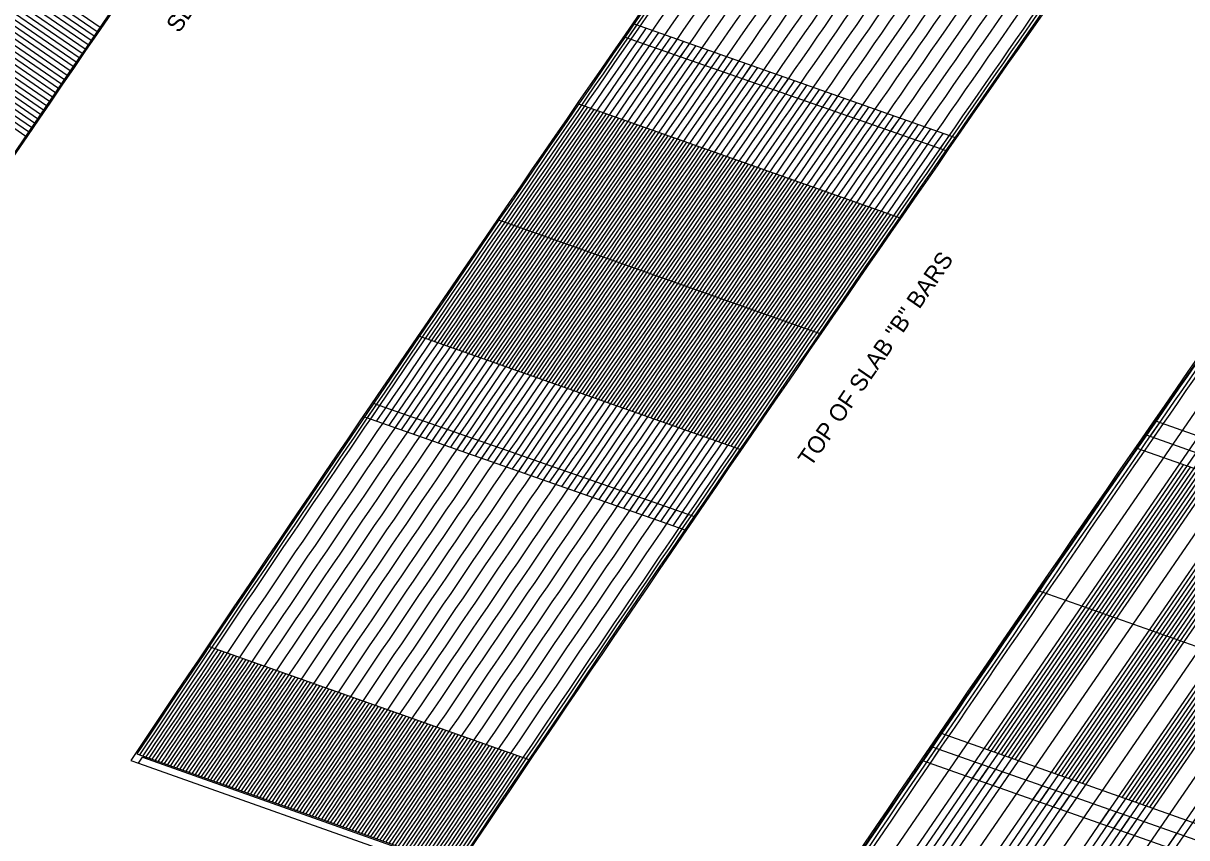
# Model space of a CAD drawing. Extents: x 2378999 to 2381348, y 331302 to 333122.
# Drawn here: x 2379768 to 2379905.9, y 332266.3 to 332362.9 of the extents above; entities that cross this region are included whole.
import ezdxf

# ---------------------------------------------------------------- set-up
doc = ezdxf.new("R2010")
doc.units = 0
for name, color, linetype in [('Arrowhead Terminators', 7, 'Continuous'), ('Mis Work Point CELL', 7, 'Continuous'), ('Old_Level_8', 7, 'Continuous'), ('P_SMU_Concrete_Barrier_Rail', 7, 'Continuous'), ('P_SMU_Mis_L_Lines', 7, 'Continuous'), ('P_SMU_Mis_Long_Chord', 7, 'Continuous'), ('P_SMU_Rebar_B_Bar', 7, 'Continuous'), ('Scratch_Level_0', 7, 'Continuous'), ('Sup Concrete Slab Lines', 7, 'Continuous')]:
    doc.layers.add(name, color=color, linetype=linetype)

msp = doc.modelspace()

# ---------------------------------------------------------------- linework, layer by layer
at = {"layer": 'Arrowhead Terminators'}
for p, q in [((2379879.71, 332273.67), (2379907.36, 332313.92)), ((2379880.53, 332273.39), (2379908.18, 332313.63)), ((2379881.34, 332273.1), (2379908.99, 332313.35)), ((2379882.15, 332272.81), (2379909.8, 332313.06)), ((2379882.97, 332272.52), (2379910.62, 332312.77)), ((2379883.78, 332272.23), (2379911.43, 332312.48)), ((2379887.68, 332270.85), (2379915.34, 332311.1)), ((2379882.34, 332276.76), (2379905.55, 332310.55)), ((2379883.15, 332276.47), (2379906.37, 332310.26)), ((2379883.96, 332276.18), (2379907.18, 332309.97)), ((2379884.78, 332275.89), (2379907.99, 332309.69)), ((2379888.5, 332270.56), (2379916.15, 332310.81)), ((2379889.31, 332270.28), (2379916.96, 332310.53)), ((2379890.12, 332269.99), (2379917.78, 332310.24)), ((2379890.94, 332269.7), (2379918.59, 332309.95)), ((2379885.59, 332275.61), (2379908.81, 332309.4)), ((2379891.75, 332269.41), (2379919.4, 332309.66)), ((2379890.31, 332273.94), (2379913.52, 332307.73)), ((2379891.12, 332273.65), (2379914.34, 332307.44)), ((2379891.93, 332273.36), (2379915.15, 332307.15)), ((2379895.65, 332268.03), (2379923.31, 332308.28)), ((2379896.47, 332267.74), (2379924.12, 332307.99)), ((2379897.28, 332267.46), (2379924.93, 332307.7)), ((2379898.09, 332267.17), (2379925.75, 332307.42)), ((2379898.91, 332266.88), (2379926.56, 332307.13)), ((2379892.75, 332273.07), (2379915.96, 332306.87)), ((2379893.56, 332272.78), (2379916.78, 332306.58)), ((2379899.72, 332266.59), (2379927.37, 332306.84)), ((2379898.28, 332271.12), (2379921.49, 332304.91)), ((2379899.09, 332270.83), (2379922.31, 332304.62)), ((2379899.9, 332270.54), (2379923.12, 332304.33)), ((2379903.62, 332265.21), (2379931.28, 332305.46)), ((2379904.44, 332264.92), (2379932.09, 332305.17)), ((2379900.72, 332270.25), (2379923.93, 332304.04)), ((2379901.53, 332269.96), (2379924.75, 332303.76)), ((2379850.18, 332230.68), (2379880.84, 332275.32)), ((2379850.99, 332230.39), (2379881.66, 332275.03)), ((2379851.8, 332230.11), (2379882.47, 332274.75)), ((2379852.61, 332229.82), (2379883.28, 332274.46)), ((2379853.43, 332229.53), (2379884.1, 332274.17)), ((2379854.24, 332229.24), (2379884.91, 332273.88)), ((2379858.15, 332227.86), (2379888.81, 332272.5)), ((2379858.96, 332227.57), (2379889.63, 332272.21)), ((2379859.77, 332227.29), (2379890.44, 332271.92)), ((2379860.59, 332227), (2379891.25, 332271.64)), ((2379861.4, 332226.71), (2379892.07, 332271.35)), ((2379862.21, 332226.42), (2379892.88, 332271.06)), ((2379866.12, 332225.04), (2379896.78, 332269.68)), ((2379866.93, 332224.75), (2379897.6, 332269.39)), ((2379867.74, 332224.46), (2379898.41, 332269.1)), ((2379868.56, 332224.18), (2379899.22, 332268.82)), ((2379869.37, 332223.89), (2379900.04, 332268.53)), ((2379870.18, 332223.6), (2379900.85, 332268.24)), ((2379874.09, 332222.22), (2379904.76, 332266.86)), ((2379874.9, 332221.93), (2379905.57, 332266.57))]:
    msp.add_line(p, q, dxfattribs=at)
for centre, radius, start, end in [((2385678.87, 328323.64), 7099.13, 144.933691, 145.338143), ((2385678.87, 328323.64), 7098.75, 144.932847, 145.337324), ((2385678.87, 328323.64), 7097.25, 144.929472, 145.334043), ((2385678.87, 328323.64), 7095.75, 144.926095, 145.330761), ((2385678.87, 328323.64), 7094.25, 144.922716, 145.327478), ((2385678.87, 328323.64), 7092.75, 144.919336, 145.324193), ((2385678.87, 328323.64), 7091.25, 144.915954, 145.320907), ((2385678.87, 328323.64), 7089.75, 144.912571, 145.317619), ((2385678.87, 328323.64), 7088.25, 144.909187, 145.31433), ((2385678.87, 328323.64), 7086.75, 144.9058, 145.31104), ((2385678.87, 328323.64), 7085.25, 144.902413, 145.307748), ((2385678.87, 328323.64), 7083.75, 144.899024, 145.304454), ((2385678.87, 328323.64), 7082.25, 144.895633, 145.301159), ((2385678.87, 328323.64), 7080.75, 144.892241, 145.297863), ((2385678.87, 328323.64), 7079.25, 144.888848, 145.294565), ((2385678.87, 328323.64), 7077.75, 144.885453, 145.291266), ((2385678.87, 328323.64), 7076.25, 144.882056, 145.287965), ((2385678.87, 328323.64), 7074.75, 144.878658, 145.284663), ((2385678.87, 328323.64), 7073.25, 144.875259, 145.28136), ((2385678.87, 328323.64), 7071.75, 144.871858, 145.278055), ((2385678.87, 328323.64), 7070.25, 144.868455, 145.274748), ((2385678.87, 328323.64), 7068.75, 144.865051, 145.27144), ((2385678.87, 328323.64), 7067.25, 144.861645, 145.268131), ((2385678.87, 328323.64), 7065.75, 144.858238, 145.26482), ((2385678.87, 328323.64), 7064.25, 144.85483, 145.261508), ((2385678.87, 328323.64), 7062.75, 144.85142, 145.258194), ((2385678.87, 328323.64), 7061.25, 144.848008, 145.254879), ((2385678.87, 328323.64), 7060.88, 144.847155, 145.25405), ((2385678.87, 328323.64), 7099.13, 145.322674, 145.778676), ((2385678.87, 328323.64), 7098.75, 145.321854, 145.777879), ((2385678.87, 328323.64), 7098, 145.320212, 145.776286), ((2385678.87, 328323.64), 7097.25, 145.31857, 145.774692), ((2385678.87, 328323.64), 7096.5, 145.316927, 145.773098), ((2385678.87, 328323.64), 7095.75, 145.315285, 145.771503), ((2385678.87, 328323.64), 7095, 145.313642, 145.769908), ((2385678.87, 328323.64), 7094.25, 145.311998, 145.768313), ((2385678.87, 328323.64), 7093.5, 145.310354, 145.766717), ((2385678.87, 328323.64), 7092.75, 145.30871, 145.765121), ((2385678.87, 328323.64), 7092, 145.307066, 145.763525), ((2385678.87, 328323.64), 7091.25, 145.305421, 145.761928), ((2385678.87, 328323.64), 7090.5, 145.303775, 145.760331), ((2385678.87, 328323.64), 7089.75, 145.30213, 145.758734), ((2385678.87, 328323.64), 7089, 145.300484, 145.757136), ((2385678.87, 328323.64), 7088.25, 145.298837, 145.755538), ((2385678.87, 328323.64), 7087.5, 145.297191, 145.75394), ((2385678.87, 328323.64), 7086.75, 145.295544, 145.752341), ((2385678.87, 328323.64), 7086, 145.293896, 145.750742), ((2385742.82, 328279.7), 7099.38, 144.934254, 145.370258), ((2385742.82, 328279.7), 7098.96, 144.933316, 145.369348), ((2385742.82, 328279.7), 7098.54, 144.932379, 145.368438), ((2385678.87, 328323.64), 7085.25, 145.292248, 145.749142), ((2385678.87, 328323.64), 7084.5, 145.2906, 145.747543), ((2385678.87, 328323.64), 7083.75, 145.288952, 145.745942), ((2385678.87, 328323.64), 7083, 145.287303, 145.744342), ((2385678.87, 328323.64), 7082.25, 145.285653, 145.742741), ((2385678.87, 328323.64), 7081.5, 145.284004, 145.74114), ((2385678.87, 328323.64), 7080.75, 145.282354, 145.739538), ((2385678.87, 328323.64), 7080, 145.280703, 145.737936), ((2385678.87, 328323.64), 7079.25, 145.279053, 145.736334), ((2385678.87, 328323.64), 7078.5, 145.277402, 145.734731), ((2385678.87, 328323.64), 7077.75, 145.27575, 145.733129), ((2385678.87, 328323.64), 7077, 145.274098, 145.731525), ((2385678.87, 328323.64), 7076.25, 145.272446, 145.729922), ((2385678.87, 328323.64), 7075.5, 145.270794, 145.728317), ((2385678.87, 328323.64), 7074.75, 145.269141, 145.726713), ((2385678.87, 328323.64), 7074, 145.267488, 145.725108), ((2385678.87, 328323.64), 7098.38, 145.41453, 145.683586), ((2385678.87, 328323.64), 7097.63, 145.412898, 145.681982), ((2385678.87, 328323.64), 7073.25, 145.265834, 145.723503), ((2385678.87, 328323.64), 7072.5, 145.26418, 145.721898), ((2385678.87, 328323.64), 7071.75, 145.262526, 145.720292), ((2385678.87, 328323.64), 7071, 145.260871, 145.718686), ((2385678.87, 328323.64), 7070.25, 145.259216, 145.717079), ((2385678.87, 328323.64), 7069.5, 145.25756, 145.715473), ((2385678.87, 328323.64), 7096.88, 145.411265, 145.680378), ((2385678.87, 328323.64), 7096.13, 145.409633, 145.678774), ((2385678.87, 328323.64), 7095.38, 145.408, 145.677169), ((2385678.87, 328323.64), 7094.63, 145.406366, 145.675564), ((2385678.87, 328323.64), 7093.88, 145.404732, 145.673959), ((2385678.87, 328323.64), 7093.13, 145.403098, 145.672353), ((2385678.87, 328323.64), 7068.75, 145.255905, 145.713865), ((2385678.87, 328323.64), 7068, 145.254249, 145.712258), ((2385678.87, 328323.64), 7067.25, 145.252592, 145.71065), ((2385678.87, 328323.64), 7066.5, 145.250935, 145.709042), ((2385678.87, 328323.64), 7065.75, 145.249278, 145.707433), ((2385678.87, 328323.64), 7092.38, 145.401464, 145.670747), ((2385678.87, 328323.64), 7091.63, 145.399829, 145.669141), ((2385678.87, 328323.64), 7090.88, 145.398194, 145.667534), ((2385678.87, 328323.64), 7090.13, 145.396558, 145.665927), ((2385678.87, 328323.64), 7089.38, 145.394922, 145.66432), ((2385678.87, 328323.64), 7065, 145.24762, 145.705824), ((2385678.87, 328323.64), 7064.25, 145.245962, 145.704215), ((2385678.87, 328323.64), 7063.5, 145.244304, 145.702605), ((2385678.87, 328323.64), 7062.75, 145.242645, 145.700995), ((2385678.87, 328323.64), 7062, 145.240986, 145.699385), ((2385678.87, 328323.64), 7088.63, 145.393286, 145.662712), ((2385678.87, 328323.64), 7087.88, 145.391649, 145.661104), ((2385678.87, 328323.64), 7087.13, 145.390012, 145.659495), ((2385678.87, 328323.64), 7086.38, 145.388375, 145.657886), ((2385678.87, 328323.64), 7085.63, 145.386737, 145.656277), ((2385678.87, 328323.64), 7061.25, 145.239327, 145.697774), ((2385678.87, 328323.64), 7060.88, 145.238497, 145.696969), ((2385678.87, 328323.64), 7084.88, 145.385099, 145.654668), ((2385678.87, 328323.64), 7084.13, 145.383461, 145.653058), ((2385678.87, 328323.64), 7083.38, 145.381822, 145.651447), ((2385678.87, 328323.64), 7082.63, 145.380183, 145.649837), ((2385678.87, 328323.64), 7081.88, 145.378543, 145.648226), ((2385678.87, 328323.64), 7081.13, 145.376903, 145.646615), ((2385678.87, 328323.64), 7080.38, 145.375263, 145.645003), ((2385678.87, 328323.64), 7079.63, 145.373623, 145.643391), ((2385678.87, 328323.64), 7078.88, 145.371982, 145.641778), ((2385678.87, 328323.64), 7078.13, 145.37034, 145.640166), ((2385678.87, 328323.64), 7077.38, 145.368699, 145.638553), ((2385678.87, 328323.64), 7076.63, 145.367057, 145.636939), ((2385678.87, 328323.64), 7075.88, 145.365414, 145.635325), ((2385678.87, 328323.64), 7075.13, 145.363771, 145.633711), ((2385678.87, 328323.64), 7074.38, 145.362128, 145.632097), ((2385678.87, 328323.64), 7073.63, 145.360485, 145.630482), ((2385678.87, 328323.64), 7072.88, 145.358841, 145.628867), ((2385678.87, 328323.64), 7072.13, 145.357197, 145.627251), ((2385678.87, 328323.64), 7071.38, 145.355552, 145.625635), ((2385678.87, 328323.64), 7070.63, 145.353907, 145.624019), ((2385678.87, 328323.64), 7069.88, 145.352262, 145.622402), ((2385678.87, 328323.64), 7069.13, 145.350616, 145.620785), ((2385678.87, 328323.64), 7068.38, 145.34897, 145.619168), ((2385678.87, 328323.64), 7067.63, 145.347324, 145.61755), ((2385678.87, 328323.64), 7066.88, 145.345677, 145.615932), ((2385678.87, 328323.64), 7066.13, 145.34403, 145.614314), ((2385678.87, 328323.64), 7065.38, 145.342383, 145.612695), ((2385678.87, 328323.64), 7064.63, 145.340735, 145.611076), ((2385678.87, 328323.64), 7063.88, 145.339087, 145.609456), ((2385678.87, 328323.64), 7063.13, 145.337438, 145.607837), ((2385678.87, 328323.64), 7062.38, 145.335789, 145.606216), ((2385678.87, 328323.64), 7061.63, 145.33414, 145.604596), ((2385678.87, 328323.64), 7099.13, 145.763207, 146.167718), ((2385678.87, 328323.64), 7098.75, 145.762409, 146.166944), ((2385678.87, 328323.64), 7097.25, 145.759219, 146.163848), ((2385678.87, 328323.64), 7095.75, 145.756027, 146.16075), ((2385678.87, 328323.64), 7094.25, 145.752833, 146.157651), ((2385678.87, 328323.64), 7092.75, 145.749638, 146.154551), ((2385742.82, 328279.7), 7099.38, 145.354106, 145.748141), ((2385742.82, 328279.7), 7098.96, 145.353195, 145.747255), ((2385742.82, 328279.7), 7098.54, 145.352284, 145.746369), ((2385678.87, 328323.64), 7091.25, 145.746442, 146.15145), ((2385678.87, 328323.64), 7089.75, 145.743244, 146.148347), ((2385678.87, 328323.64), 7088.25, 145.740045, 146.145242), ((2385678.87, 328323.64), 7086.75, 145.736845, 146.142136), ((2385678.87, 328323.64), 7085.25, 145.733643, 146.139029), ((2385678.87, 328323.64), 7083.75, 145.73044, 146.135921), ((2385678.87, 328323.64), 7082.25, 145.727235, 146.132811), ((2385678.87, 328323.64), 7080.75, 145.724029, 146.1297), ((2385678.87, 328323.64), 7079.25, 145.720822, 146.126588), ((2385678.87, 328323.64), 7077.75, 145.717613, 146.123474), ((2385678.87, 328323.64), 7076.25, 145.714402, 146.120359), ((2385678.87, 328323.64), 7074.75, 145.711191, 146.117242), ((2385678.87, 328323.64), 7073.25, 145.707978, 146.114124), ((2385678.87, 328323.64), 7071.75, 145.704763, 146.111005), ((2385678.87, 328323.64), 7070.25, 145.701547, 146.107884), ((2385678.87, 328323.64), 7068.75, 145.69833, 146.104762), ((2385678.87, 328323.64), 7067.25, 145.695111, 146.101638), ((2385678.87, 328323.64), 7065.75, 145.691891, 146.098514), ((2385678.87, 328323.64), 7064.25, 145.688669, 146.095388), ((2385678.87, 328323.64), 7062.75, 145.685446, 146.09226), ((2385678.87, 328323.64), 7061.25, 145.682222, 146.089131), ((2385678.87, 328323.64), 7060.88, 145.681416, 146.088349), ((2385643.84, 328336.04), 7062.38, 145.967039, 146.091478), ((2385643.84, 328336.04), 7062, 145.966251, 146.090696), ((2385643.84, 328336.04), 7061.63, 145.965462, 146.089913), ((2385645.3, 328335.52), 7062.38, 145.967041, 146.091478), ((2385645.3, 328335.52), 7062, 145.966252, 146.090696), ((2385645.3, 328335.52), 7061.63, 145.965463, 146.089913), ((2385646.76, 328335), 7062.38, 145.967043, 146.091478), ((2385646.76, 328335), 7062, 145.966254, 146.090696), ((2385646.76, 328335), 7061.63, 145.965465, 146.089913), ((2385648.21, 328334.49), 7062.38, 145.967045, 146.091478), ((2385648.21, 328334.49), 7062, 145.966256, 146.090696), ((2385648.21, 328334.49), 7061.63, 145.965467, 146.089913), ((2385649.67, 328333.97), 7062.38, 145.967046, 146.091478), ((2385649.67, 328333.97), 7062, 145.966258, 146.090696), ((2385649.67, 328333.97), 7061.63, 145.965469, 146.089913), ((2385651.13, 328333.45), 7062.38, 145.967048, 146.091478), ((2385651.13, 328333.45), 7062, 145.966259, 146.090696), ((2385651.13, 328333.45), 7061.63, 145.96547, 146.089913), ((2385652.59, 328332.94), 7062.38, 145.96705, 146.091478), ((2385652.59, 328332.94), 7062, 145.966261, 146.090696), ((2385652.59, 328332.94), 7061.63, 145.965472, 146.089913), ((2385654.05, 328332.42), 7062.38, 145.967052, 146.091478), ((2385654.05, 328332.42), 7062, 145.966263, 146.090696), ((2385654.05, 328332.42), 7061.63, 145.965474, 146.089913), ((2385655.51, 328331.9), 7062.38, 145.967053, 146.091478), ((2385655.51, 328331.9), 7062, 145.966265, 146.090696), ((2385655.51, 328331.9), 7061.63, 145.965476, 146.089913), ((2385656.97, 328331.39), 7062.38, 145.967055, 146.091478), ((2385656.97, 328331.39), 7062, 145.966266, 146.090696), ((2385656.97, 328331.39), 7061.63, 145.965477, 146.089913), ((2385658.43, 328330.87), 7062.38, 145.967057, 146.091478), ((2385658.43, 328330.87), 7062, 145.966268, 146.090696), ((2385658.43, 328330.87), 7061.63, 145.965479, 146.089913), ((2385659.89, 328330.35), 7062.38, 145.967059, 146.091478), ((2385659.89, 328330.35), 7062, 145.96627, 146.090696), ((2385659.89, 328330.35), 7061.63, 145.965481, 146.089913), ((2385661.35, 328329.84), 7062.38, 145.96706, 146.091478), ((2385661.35, 328329.84), 7062, 145.966272, 146.090696), ((2385661.35, 328329.84), 7061.63, 145.965483, 146.089913), ((2385662.81, 328329.32), 7062.38, 145.967062, 146.091478), ((2385662.81, 328329.32), 7062, 145.966273, 146.090696), ((2385662.81, 328329.32), 7061.63, 145.965484, 146.089913), ((2385664.27, 328328.8), 7062.38, 145.967064, 146.091478), ((2385664.27, 328328.8), 7062, 145.966275, 146.090696), ((2385664.27, 328328.8), 7061.63, 145.965486, 146.089913), ((2385665.73, 328328.29), 7062.38, 145.967066, 146.091478), ((2385665.73, 328328.29), 7062, 145.966277, 146.090696), ((2385665.73, 328328.29), 7061.63, 145.965488, 146.089913), ((2385667.19, 328327.77), 7062.38, 145.967067, 146.091478), ((2385667.19, 328327.77), 7062, 145.966279, 146.090696), ((2385667.19, 328327.77), 7061.63, 145.96549, 146.089913), ((2385668.65, 328327.25), 7062.38, 145.967069, 146.091478), ((2385668.65, 328327.25), 7062, 145.96628, 146.090696), ((2385668.65, 328327.25), 7061.63, 145.965491, 146.089913), ((2385670.11, 328326.74), 7062.38, 145.967071, 146.091478), ((2385670.11, 328326.74), 7062, 145.966282, 146.090696), ((2385670.11, 328326.74), 7061.63, 145.965493, 146.089913), ((2385671.57, 328326.22), 7062.38, 145.967073, 146.091478), ((2385671.57, 328326.22), 7062, 145.966284, 146.090696), ((2385671.57, 328326.22), 7061.63, 145.965495, 146.089913), ((2385673.03, 328325.7), 7062.38, 145.967074, 146.091478), ((2385673.03, 328325.7), 7062, 145.966286, 146.090696), ((2385673.03, 328325.7), 7061.63, 145.965497, 146.089913), ((2385674.49, 328325.19), 7062.38, 145.967076, 146.091478), ((2385674.49, 328325.19), 7062, 145.966287, 146.090696), ((2385674.49, 328325.19), 7061.63, 145.965498, 146.089913), ((2385675.95, 328324.67), 7062.38, 145.967078, 146.091478), ((2385675.95, 328324.67), 7062, 145.966289, 146.090696), ((2385675.95, 328324.67), 7061.63, 145.9655, 146.089913), ((2385677.41, 328324.15), 7062.38, 145.96708, 146.091478), ((2385677.41, 328324.15), 7062, 145.966291, 146.090696), ((2385742.82, 328279.7), 7099.38, 145.732017, 146.168234), ((2385742.82, 328279.7), 7098.96, 145.73113, 146.167374), ((2385742.82, 328279.7), 7098.54, 145.730243, 146.166514), ((2385677.41, 328324.15), 7061.63, 145.965502, 146.089913), ((2385678.87, 328323.64), 7062.38, 145.967081, 146.091478), ((2385678.87, 328323.64), 7062, 145.966293, 146.090696), ((2385678.87, 328323.64), 7061.63, 145.965504, 146.089913)]:
    msp.add_arc(centre, radius, start, end, dxfattribs=at)
at = {"layer": 'Mis Work Point CELL'}
for p, q in [((2379824.25, 332339.62), (2379862.56, 332326.06)), ((2379888.21, 332295.69), (2379926.51, 332282.13))]:
    msp.add_line(p, q, dxfattribs=at)
at = {"layer": 'Old_Level_8'}
for p, q in [((2379745.06, 332384.46), (2379777.14, 332362.43)), ((2379744.01, 332382.92), (2379776.08, 332360.88)), ((2379744.36, 332383.43), (2379776.43, 332361.39)), ((2379744.71, 332383.95), (2379776.79, 332361.91)), ((2379743.3, 332381.88), (2379775.38, 332359.85)), ((2379743.65, 332382.4), (2379775.73, 332360.36)), ((2379742.24, 332380.34), (2379774.32, 332358.3)), ((2379742.59, 332380.85), (2379774.67, 332358.81)), ((2379742.95, 332381.37), (2379775.02, 332359.33)), ((2379741.18, 332378.79), (2379773.26, 332356.75)), ((2379741.54, 332379.3), (2379773.61, 332357.27)), ((2379741.89, 332379.82), (2379773.97, 332357.78)), ((2379740.48, 332377.76), (2379772.56, 332355.72)), ((2379740.83, 332378.27), (2379772.91, 332356.23)), ((2379739.42, 332376.21), (2379771.5, 332354.17)), ((2379739.78, 332376.72), (2379771.85, 332354.69)), ((2379740.13, 332377.24), (2379772.2, 332355.2)), ((2379738.37, 332374.66), (2379770.44, 332352.62)), ((2379738.72, 332375.17), (2379770.79, 332353.14)), ((2379739.07, 332375.69), (2379771.15, 332353.65)), ((2379737.31, 332373.11), (2379769.39, 332351.07)), ((2379737.66, 332373.62), (2379769.74, 332351.59)), ((2379738.01, 332374.14), (2379770.09, 332352.1)), ((2379736.61, 332372.07), (2379768.68, 332350.04)), ((2379736.96, 332372.59), (2379769.03, 332350.55)), ((2379736.25, 332371.56), (2379768.33, 332349.52))]:
    msp.add_line(p, q, dxfattribs=at)
at = {"layer": 'P_SMU_Concrete_Barrier_Rail'}
for p, q in [((2379780.77, 332275.49), (2379781.71, 332275.16)), ((2379781.71, 332275.16), (2379782.18, 332275.87)), ((2379782.18, 332275.87), (2379818.52, 332263.01)), ((2379782.83, 332275.64), (2379782.18, 332275.87))]:
    msp.add_line(p, q, dxfattribs=at)
for centre, radius, start, end in [((2385604, 328375.08), 7099.63, 144.926438, 146.177079), ((2385604, 328375.08), 7060.38, 144.837589, 146.095684), ((2385678.87, 328323.64), 7099.63, 144.926438, 146.177079), ((2385678.87, 328323.64), 7060.38, 144.837589, 146.095684), ((2385742.82, 328279.7), 7099.63, 144.926438, 146.177079), ((2385742.82, 328279.7), 7060.38, 144.837589, 146.095684)]:
    msp.add_arc(centre, radius, start, end, dxfattribs=at)
at = {"layer": 'P_SMU_Mis_L_Lines'}
for p, q in [((2379891.59, 332294.49), (2379935.41, 332358.27)), ((2379899.56, 332291.67), (2379943.38, 332355.45)), ((2379847.64, 332230.52), (2379891.59, 332294.49)), ((2379855.61, 332227.7), (2379899.56, 332291.67)), ((2379863.58, 332224.88), (2379907.53, 332288.85)), ((2379871.55, 332222.06), (2379915.5, 332286.03))]:
    msp.add_line(p, q, dxfattribs=at)
at = {"layer": 'P_SMU_Mis_Long_Chord'}
msp.add_arc((2385604, 328375.08), 7080, 144.882142, 146.136498, dxfattribs=at)
at = {"layer": 'P_SMU_Rebar_B_Bar'}
msp.add_line((2379781.71, 332275.16), (2379818.04, 332262.3), dxfattribs=at)
at = {"layer": 'Scratch_Level_0'}
for p, q in [((2379840.44, 332362.83), (2379878.46, 332349.36)), ((2379839.35, 332361.25), (2379877.37, 332347.79)), ((2379871.86, 332339.84), (2379833.86, 332353.3)), ((2379815.01, 332325.81), (2379852.97, 332312.38)), ((2379847.51, 332304.4), (2379809.56, 332317.82)), ((2379808.48, 332316.24), (2379846.43, 332302.82)), ((2379902.22, 332315.74), (2379940.23, 332302.29)), ((2379901.09, 332314.1), (2379939.1, 332300.64)), ((2379899.99, 332312.52), (2379938, 332299.07)), ((2379790.06, 332289.02), (2379827.95, 332275.6)), ((2379876.8, 332278.72), (2379914.75, 332265.28)), ((2379875.73, 332277.13), (2379913.68, 332263.7)), ((2379781.51, 332276.29), (2379819.38, 332262.88)), ((2379874.6, 332275.48), (2379912.55, 332262.05))]:
    msp.add_line(p, q, dxfattribs=at)
for centre, radius, start, end in [((2385604, 328375.08), 7099.46, 144.934441, 146.168406), ((2385604, 328375.08), 7060.54, 144.846397, 146.087653), ((2385678.87, 328323.64), 7099.46, 144.934441, 146.168406), ((2385678.87, 328323.64), 7060.54, 144.846397, 146.087653), ((2385742.82, 328279.7), 7099.46, 144.934441, 146.168406), ((2385742.82, 328279.7), 7060.54, 144.846397, 146.087653)]:
    msp.add_arc(centre, radius, start, end, dxfattribs=at)

# ---------------------------------------------------------------- texts
at = {"layer": 'Sup Concrete Slab Lines'}
for s, p in [('SLAB "A" BARS', (2379786.49, 332361.63)), ('TOP OF SLAB "B" BARS', (2379861.36, 332310.19))]:
    msp.add_text(s, height=2, rotation=55.5093, dxfattribs=at).set_placement(p)

doc.saveas('drawing.dxf')
